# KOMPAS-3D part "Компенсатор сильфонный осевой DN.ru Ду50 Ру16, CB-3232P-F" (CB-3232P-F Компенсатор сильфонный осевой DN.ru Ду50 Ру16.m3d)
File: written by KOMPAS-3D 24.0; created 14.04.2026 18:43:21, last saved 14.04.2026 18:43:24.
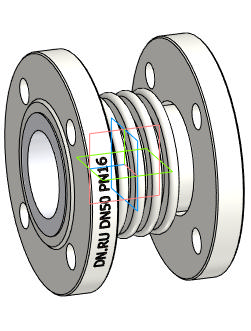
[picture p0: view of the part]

Document properties: Автор: DN.RU; Полное имя файла: D:\PROJECT CAD\DN.RU\..199(ACTUALE). CB-3232P-F Компенсатор сильфонный осевой DN.ru\Исходники\DN50\CB-3232P-F Компенсатор сильфонный осевой DN.ru Ду50 Ру16.m3d

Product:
- Body: Твердое тело1  | qty 1
    Масса: 6.460413
- Part/product: Компенсатор сильфонный осевой DN.ru Ду50 Ру16  | designation CB-3232P-F
    Масса: 5
    Раздел спецификации: Прочие изделия
    Комментарий: D140-02138
    Примечание: D140-02138
    additional columns: Типовые

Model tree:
1. Твердое тело1  (labels: Твердое тело1)

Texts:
  CB-3232P-F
